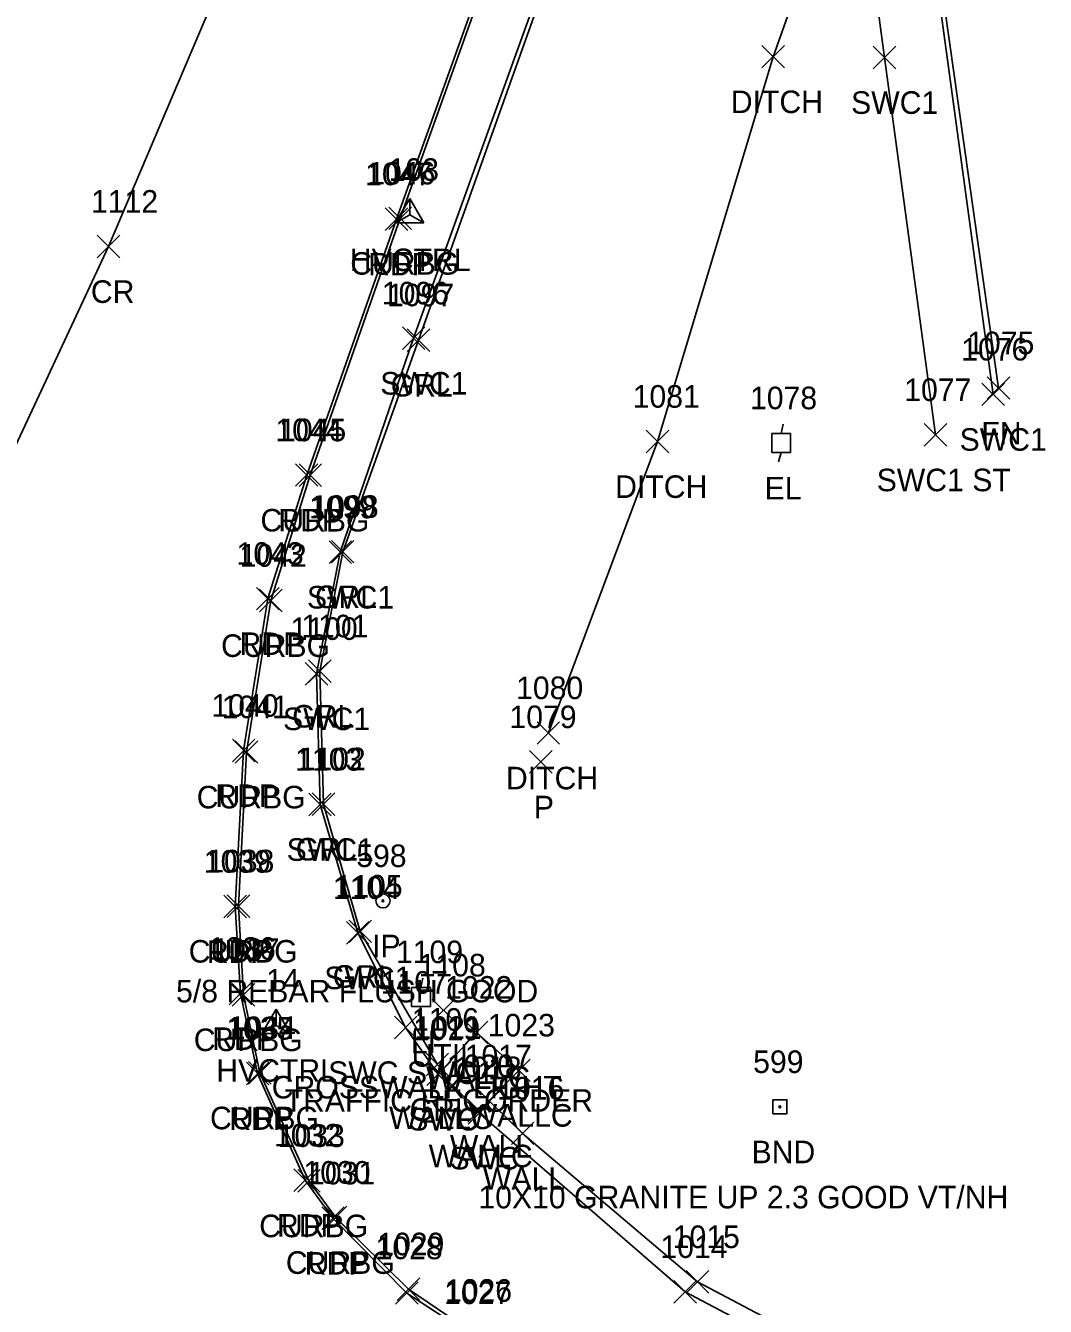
# Model space of a CAD drawing. Extents: x 1690689 to 1696275, y 438760 to 444007.
# Drawn here: x 1693096.4 to 1693186.8, y 438847.7 to 438961.2 of the extents above; entities that cross this region are included whole.
import ezdxf

# ---------------------------------------------------------------- set-up
doc = ezdxf.new("R2010")
doc.units = 0
for name, color, linetype in [('C_A', 7, 'Continuous'), ('C_I', 7, 'Continuous'), ('CPSM', 7, 'Continuous'), ('D_A', 7, 'Continuous'), ('D_I', 7, 'Continuous'), ('D_TIC', 7, 'Continuous'), ('DD', 7, 'Continuous'), ('L_A', 7, 'Continuous'), ('L_I', 7, 'Continuous'), ('L_TIC', 7, 'Continuous'), ('Level 18', 7, 'Continuous'), ('LFNC', 7, 'Continuous'), ('LW', 7, 'Continuous'), ('M_A', 7, 'Continuous'), ('M_C', 7, 'Continuous'), ('M_I', 7, 'Continuous'), ('MPIR', 7, 'Continuous'), ('P_A', 7, 'Continuous'), ('P_I', 7, 'Continuous'), ('P_TIC', 7, 'Continuous'), ('PET', 7, 'Continuous'), ('PRC', 7, 'Continuous'), ('R_A', 7, 'Continuous'), ('R_I', 7, 'Continuous'), ('R_TIC', 7, 'Continuous'), ('RC', 7, 'Continuous'), ('RGR', 7, 'Continuous'), ('RSW', 7, 'Continuous'), ('U_A', 7, 'Continuous'), ('U_C', 7, 'Continuous'), ('U_I', 7, 'Continuous'), ('UDEFAULT', 7, 'Continuous'), ('UEPT', 7, 'Continuous'), ('ULP', 7, 'Continuous')]:
    doc.layers.add(name, color=color, linetype=linetype)

msp = doc.modelspace()

# ---------------------------------------------------------------- linework, layer by layer
at = {"layer": 'CPSM'}
for p, q in [((1693129.22, 438943.73), (1693130.47, 438945.9)), ((1693131.72, 438943.73), (1693130.47, 438945.9)), ((1693130.47, 438944.46), (1693130.47, 438945.9)), ((1693129.22, 438943.73), (1693130.47, 438944.46)), ((1693130.47, 438944.46), (1693130.47, 438944.46)), ((1693130.47, 438944.46), (1693131.72, 438943.73)), ((1693129.22, 438943.73), (1693131.72, 438943.73)), ((1693117.37, 438871.85), (1693118.62, 438874.02)), ((1693119.87, 438871.85), (1693118.62, 438874.02)), ((1693118.62, 438872.58), (1693118.62, 438874.02)), ((1693117.37, 438871.85), (1693118.62, 438872.58)), ((1693118.62, 438872.58), (1693118.62, 438872.58)), ((1693118.62, 438872.58), (1693119.87, 438871.85)), ((1693117.37, 438871.85), (1693119.87, 438871.85))]:
    msp.add_line(p, q, dxfattribs=at)
at = {"layer": 'D_TIC'}
for points in [[(1693161.69, 438957.47), (1693163.69, 438959.47)], [(1693163.69, 438957.47), (1693161.69, 438959.47)], [(1693151.44, 438923.35), (1693153.44, 438925.35)], [(1693153.44, 438923.35), (1693151.44, 438925.35)], [(1693141.76, 438897.51), (1693143.76, 438899.51)], [(1693143.76, 438897.51), (1693141.76, 438899.51)], [(1693141.09, 438894.94), (1693143.09, 438896.94)], [(1693143.09, 438894.94), (1693141.09, 438896.94)]]:
    msp.add_lwpolyline(points, dxfattribs=at)
at = {"layer": 'DD'}
msp.add_lwpolyline([(1693142.76, 438898.51), (1693152.44, 438924.35), (1693162.69, 438958.47), (1693166.84, 438970.21)], dxfattribs=at)
at = {"layer": 'L_TIC'}
for points in [[(1693181.65, 438928.09), (1693183.65, 438930.09)], [(1693183.65, 438928.09), (1693181.65, 438930.09)], [(1693135.38, 438870.95), (1693137.38, 438872.95)], [(1693137.38, 438870.95), (1693135.38, 438872.95)], [(1693132.1, 438867.38), (1693134.1, 438869.38)], [(1693134.1, 438867.38), (1693132.1, 438869.38)], [(1693139.16, 438867.6), (1693141.16, 438869.6)], [(1693141.16, 438867.6), (1693139.16, 438869.6)], [(1693136.55, 438864.86), (1693138.55, 438866.86)], [(1693138.55, 438864.86), (1693136.55, 438866.86)], [(1693135.61, 438864), (1693137.61, 438866)], [(1693137.61, 438864), (1693135.61, 438866)], [(1693139.48, 438862.01), (1693141.48, 438864.01)], [(1693141.48, 438862.01), (1693139.48, 438864.01)], [(1693154.98, 438848.84), (1693156.98, 438850.84)], [(1693156.98, 438848.84), (1693154.98, 438850.84)]]:
    msp.add_lwpolyline(points, dxfattribs=at)
at = {"layer": 'Level 18'}
msp.add_lwpolyline([(1693162.66, 438865.99), (1693163.91, 438865.99), (1693163.91, 438864.74), (1693162.66, 438864.74)], close=True, dxfattribs=at)
msp.add_circle((1693163.28, 438865.36), 0.0833, dxfattribs=at)
at = {"layer": 'LFNC'}
msp.add_lwpolyline([(1693170.07, 439022.53), (1693176.98, 438969.21), (1693182.65, 438929.09)], dxfattribs=at)
at = {"layer": 'LW'}
for points in [[(1693136.61, 438865), (1693133.1, 438868.38), (1693136.38, 438871.95), (1693140.16, 438868.6)], [(1693140.16, 438868.6), (1693136.61, 438865)], [(1693176.44, 438840.23), (1693169.95, 438842.46), (1693155.98, 438849.84), (1693140.48, 438863.01), (1693137.55, 438865.86)]]:
    msp.add_lwpolyline(points, dxfattribs=at)
at = {"layer": 'MPIR'}
for radius in [0.625, 0.0833]:
    msp.add_circle((1693128.1, 438883.62), radius, dxfattribs=at)
at = {"layer": 'P_TIC'}
for points in [[(1693128.29, 438943.07), (1693130.29, 438945.07)], [(1693130.29, 438943.07), (1693128.29, 438945.07)], [(1693102.78, 438940.64), (1693104.78, 438942.64)], [(1693104.78, 438940.64), (1693102.78, 438942.64)], [(1693120.34, 438920.38), (1693122.34, 438922.38)], [(1693122.34, 438920.38), (1693120.34, 438922.38)], [(1693116.89, 438909.42), (1693118.89, 438911.42)], [(1693118.89, 438909.42), (1693116.89, 438911.42)], [(1693114.75, 438895.95), (1693116.75, 438897.95)], [(1693116.75, 438895.95), (1693114.75, 438897.95)], [(1693114, 438882.12), (1693116, 438884.12)], [(1693116, 438882.12), (1693114, 438884.12)], [(1693114.47, 438874.4), (1693116.47, 438876.4)], [(1693116.47, 438874.4), (1693114.47, 438876.4)], [(1693115.99, 438867.32), (1693117.99, 438869.32)], [(1693117.99, 438867.32), (1693115.99, 438869.32)], [(1693120.21, 438857.85), (1693122.21, 438859.85)], [(1693122.21, 438857.85), (1693120.21, 438859.85)], [(1693122.67, 438854.48), (1693124.67, 438856.48)], [(1693124.67, 438854.48), (1693122.67, 438856.48)], [(1693129.21, 438847.85), (1693131.21, 438849.85)], [(1693131.21, 438847.85), (1693129.21, 438849.85)]]:
    msp.add_lwpolyline(points, dxfattribs=at)
at = {"layer": 'PET'}
msp.add_lwpolyline([(1693178, 438831.35), (1693167.86, 438834.18), (1693150.55, 438839.03), (1693143.37, 438841.6), (1693136.29, 438844.87), (1693130.21, 438848.85), (1693123.67, 438855.48), (1693121.21, 438858.85), (1693116.99, 438868.32), (1693115.47, 438875.4), (1693115, 438883.12), (1693115.75, 438896.95), (1693117.89, 438910.42), (1693121.34, 438921.38), (1693129.29, 438944.07), (1693138.23, 438969.02), (1693143.65, 438986.67), (1693149.76, 439012.35), (1693154.07, 439032.19), (1693155.34, 439035.22), (1693157.21, 439037.36), (1693158.65, 439037.84), (1693160.14, 439048.77), (1693162.88, 439071.43)], dxfattribs=at)
at = {"layer": 'PRC'}
msp.add_lwpolyline([(1693075.4, 438881.17), (1693089.6, 438911.3), (1693103.78, 438941.64), (1693117.42, 438973.77), (1693128.92, 439005.9), (1693137.63, 439039.04), (1693143.37, 439073.85)], dxfattribs=at)
at = {"layer": 'R_TIC'}
for points in [[(1693171.55, 438957.4), (1693173.55, 438959.4)], [(1693173.55, 438957.4), (1693171.55, 438959.4)], [(1693128.62, 438943.14), (1693130.62, 438945.14)], [(1693130.62, 438943.14), (1693128.62, 438945.14)], [(1693129.82, 438932.51), (1693131.82, 438934.51)], [(1693131.82, 438932.51), (1693129.82, 438934.51)], [(1693130.24, 438932.34), (1693132.24, 438934.34)], [(1693132.24, 438932.34), (1693130.24, 438934.34)], [(1693181.18, 438927.53), (1693183.18, 438929.53)], [(1693183.18, 438927.53), (1693181.18, 438929.53)], [(1693176.08, 438923.94), (1693178.08, 438925.94)], [(1693178.08, 438923.94), (1693176.08, 438925.94)], [(1693120.66, 438920.37), (1693122.66, 438922.37)], [(1693122.66, 438920.37), (1693120.66, 438922.37)], [(1693123.32, 438913.54), (1693125.32, 438915.54)], [(1693125.32, 438913.54), (1693123.32, 438915.54)], [(1693123.53, 438913.58), (1693125.53, 438915.58)], [(1693125.53, 438913.58), (1693123.53, 438915.58)], [(1693117.16, 438909.25), (1693119.16, 438911.25)], [(1693119.16, 438909.25), (1693117.16, 438911.25)], [(1693121.2, 438902.76), (1693123.2, 438904.76)], [(1693123.2, 438902.76), (1693121.2, 438904.76)], [(1693121.5, 438902.99), (1693123.5, 438904.99)], [(1693123.5, 438902.99), (1693121.5, 438904.99)], [(1693115, 438895.82), (1693117, 438897.82)], [(1693117, 438895.82), (1693115, 438897.82)], [(1693121.52, 438891.17), (1693123.52, 438893.17)], [(1693123.52, 438891.17), (1693121.52, 438893.17)], [(1693121.82, 438891.2), (1693123.82, 438893.2)], [(1693123.82, 438891.2), (1693121.82, 438893.2)], [(1693114.29, 438882.15), (1693116.29, 438884.15)], [(1693116.29, 438882.15), (1693114.29, 438884.15)], [(1693124.86, 438879.79), (1693126.86, 438881.79)], [(1693126.86, 438879.79), (1693124.86, 438881.79)], [(1693125.09, 438879.92), (1693127.09, 438881.92)], [(1693127.09, 438879.92), (1693125.09, 438881.92)], [(1693114.74, 438874.3), (1693116.74, 438876.3)], [(1693116.74, 438874.3), (1693114.74, 438876.3)], [(1693129.11, 438871.39), (1693131.11, 438873.39)], [(1693131.11, 438871.39), (1693129.11, 438873.39)], [(1693129.11, 438871.39), (1693131.11, 438873.39)], [(1693131.11, 438871.39), (1693129.11, 438873.39)], [(1693131.92, 438868.11), (1693133.92, 438870.11)], [(1693133.92, 438868.11), (1693131.92, 438870.11)], [(1693116.19, 438867.37), (1693118.19, 438869.37)], [(1693118.19, 438867.37), (1693116.19, 438869.37)], [(1693131.98, 438867.26), (1693133.98, 438869.26)], [(1693133.98, 438867.26), (1693131.98, 438869.26)], [(1693135.64, 438863.81), (1693137.64, 438865.81)], [(1693137.64, 438863.81), (1693135.64, 438865.81)], [(1693120.54, 438857.8), (1693122.54, 438859.8)], [(1693122.54, 438857.8), (1693120.54, 438859.8)], [(1693122.91, 438854.55), (1693124.91, 438856.55)], [(1693124.91, 438854.55), (1693122.91, 438856.55)], [(1693129.37, 438848.2), (1693131.37, 438850.2)], [(1693131.37, 438848.2), (1693129.37, 438850.2)], [(1693153.89, 438847.96), (1693155.89, 438849.96)], [(1693155.89, 438847.96), (1693153.89, 438849.96)]]:
    msp.add_lwpolyline(points, dxfattribs=at)
at = {"layer": 'RC'}
msp.add_lwpolyline([(1693178.03, 438831.53), (1693167.9, 438834.34), (1693150.57, 438839.37), (1693143.21, 438842), (1693136.42, 438845.08), (1693130.37, 438849.2), (1693123.91, 438855.55), (1693121.54, 438858.8), (1693117.19, 438868.37), (1693115.74, 438875.3), (1693115.29, 438883.15), (1693116, 438896.82), (1693118.16, 438910.25), (1693121.66, 438921.37), (1693129.62, 438944.14), (1693138.48, 438968.95), (1693143.79, 438986.67), (1693150.08, 439012.32), (1693154.23, 439032.31)], dxfattribs=at)
at = {"layer": 'RGR'}
msp.add_lwpolyline([(1693159.79, 438999.34), (1693153.67, 438991.77), (1693151.07, 438986.95), (1693144.82, 438971.39), (1693131.24, 438933.34), (1693124.53, 438914.58), (1693122.5, 438903.99), (1693122.82, 438892.2), (1693126.09, 438880.92), (1693132.92, 438869.11)], dxfattribs=at)
at = {"layer": 'RSW'}
for points in [[(1693154.23, 439032.31), (1693155.6, 439035.22), (1693157.23, 439037.18), (1693159.3, 439037.74), (1693163.18, 439035.96), (1693167.65, 439031.6), (1693169.75, 439022.56), (1693176.65, 438969.04), (1693182.18, 438928.53)], [(1693177.08, 438924.94), (1693172.55, 438958.4), (1693164.75, 439016.33), (1693163.48, 439025.83), (1693161.01, 439030.23), (1693158.92, 439031.14), (1693149.55, 438988.8), (1693144.42, 438971.31), (1693130.82, 438933.51), (1693124.32, 438914.54), (1693122.2, 438903.76), (1693122.52, 438892.17), (1693125.86, 438880.79), (1693130.11, 438872.39)], [(1693179.46, 438837.75), (1693169.64, 438841.15), (1693154.89, 438848.96), (1693136.64, 438864.81), (1693132.98, 438868.26), (1693130.11, 438872.39)]]:
    msp.add_lwpolyline(points, dxfattribs=at)
at = {"layer": 'UDEFAULT'}
for points in [[(1693132.47, 438872.92), (1693134.47, 438874.92)], [(1693134.47, 438872.92), (1693132.47, 438874.92)]]:
    msp.add_lwpolyline(points, dxfattribs=at)
at = {"layer": 'UEPT'}
for p, q in [((1693163.56, 438925.88), (1693163.4, 438925.05)), ((1693162.56, 438923.38), (1693162.56, 438925.05)), ((1693162.56, 438925.05), (1693164.23, 438925.05)), ((1693164.23, 438925.05), (1693164.23, 438923.38)), ((1693163.4, 438924.21), (1693163.4, 438924.21)), ((1693164.23, 438923.38), (1693162.56, 438923.38)), ((1693163.15, 438922.55), (1693163.4, 438923.38))]:
    msp.add_line(p, q, dxfattribs=at)
at = {"layer": 'ULP'}
for p, q in [((1693130.63, 438874.27), (1693130.63, 438875.94)), ((1693130.63, 438875.94), (1693132.3, 438875.94)), ((1693131.63, 438876.77), (1693131.46, 438875.94)), ((1693132.3, 438875.94), (1693132.3, 438874.27)), ((1693131.46, 438875.1), (1693131.46, 438875.1)), ((1693132.3, 438874.27), (1693130.63, 438874.27)), ((1693131.21, 438873.44), (1693131.46, 438874.27))]:
    msp.add_line(p, q, dxfattribs=at)

# ---------------------------------------------------------------- texts
at = {"layer": 'C_A'}
for p in [(1693125.16, 438939.46), (1693113.32, 438867.58)]:
    msp.add_text('HVCTRL', height=2, dxfattribs=at).set_placement(p)
at = {"layer": 'C_I'}
for s, p in [('103', (1693128.6, 438947.46)), ('14', (1693117.73, 438875.57))]:
    msp.add_text(s, height=2, dxfattribs=at).set_placement(p)
at = {"layer": 'D_A'}
for s, p in [('DITCH', (1693158.93, 438953.47)), ('DITCH', (1693148.68, 438919.35)), ('DITCH', (1693139, 438893.51)), ('P', (1693141.47, 438890.94))]:
    msp.add_text(s, height=2, dxfattribs=at).set_placement(p)
at = {"layer": 'D_I'}
for s, p in [('1081', (1693150.23, 438927.35)), ('1080', (1693139.9, 438901.51)), ('1079', (1693139.31, 438898.94))]:
    msp.add_text(s, height=2, dxfattribs=at).set_placement(p)
at = {"layer": 'L_A'}
for s, p in [('FN', (1693181.13, 438924.09)), ('WALLC', (1693131.92, 438866.95)), ('WALLC', (1693135.7, 438863.6)), ('WALLC', (1693128.63, 438863.38)), ('WALL', (1693134.03, 438860.86)), ('WALLC', (1693132.15, 438860)), ('WALL', (1693136.96, 438858.01))]:
    msp.add_text(s, height=2, dxfattribs=at).set_placement(p)
at = {"layer": 'L_I'}
for s, p in [('1075', (1693179.88, 438932.09)), ('1022', (1693133.61, 438874.95)), ('1023', (1693137.39, 438871.6)), ('1021', (1693130.89, 438871.38)), ('1017', (1693135.34, 438868.86)), ('1020', (1693133.75, 438868)), ('1016', (1693138.22, 438866.01)), ('1015', (1693153.78, 438852.84))]:
    msp.add_text(s, height=2, dxfattribs=at).set_placement(p)
at = {"layer": 'M_A'}
for s, p in [('IP', (1693127.14, 438878.62)), ('BND', (1693160.77, 438860.36))]:
    msp.add_text(s, height=2, dxfattribs=at).set_placement(p)
at = {"layer": 'M_C'}
for s, p in [('5/8 REBAR FLUSH GOOD', (1693109.76, 438874.62)), ('10X10 GRANITE UP 2.3 GOOD VT/NH', (1693136.56, 438856.36))]:
    msp.add_text(s, height=2, dxfattribs=at).set_placement(p)
at = {"layer": 'M_I'}
for s, p in [('598', (1693125.73, 438886.62)), ('599', (1693160.91, 438868.36))]:
    msp.add_text(s, height=2, dxfattribs=at).set_placement(p)
at = {"layer": 'P_A'}
for s, p in [('RDP', (1693126.78, 438939.07)), ('CR', (1693102.21, 438936.64)), ('RDP', (1693118.82, 438916.38)), ('RDP', (1693115.38, 438905.42)), ('RDP', (1693113.24, 438891.95)), ('RDP', (1693112.48, 438878.12)), ('RDP', (1693112.96, 438870.4)), ('RDP', (1693114.47, 438863.32)), ('RDP', (1693118.7, 438853.85)), ('RDP', (1693121.16, 438850.48))]:
    msp.add_text(s, height=2, dxfattribs=at).set_placement(p)
at = {"layer": 'P_I'}
for s, p in [('1047', (1693126.52, 438947.07)), ('1112', (1693102.22, 438944.64)), ('1044', (1693118.56, 438924.38)), ('1043', (1693115.12, 438913.42)), ('1040', (1693112.89, 438899.95)), ('1039', (1693112.22, 438886.12)), ('1036', (1693112.65, 438878.4)), ('1035', (1693114.21, 438871.32)), ('1032', (1693118.44, 438861.85)), ('1031', (1693121.46, 438858.48)), ('1028', (1693127.44, 438851.85)), ('1027', (1693133.52, 438847.87))]:
    msp.add_text(s, height=2, dxfattribs=at).set_placement(p)
at = {"layer": 'R_A'}
for s, p in [('SWC1', (1693169.59, 438953.4)), ('CURBG', (1693125.2, 438939.14)), ('SWC1', (1693127.86, 438928.51)), ('GRL', (1693128.78, 438928.34)), ('SWC1', (1693179.21, 438923.53)), ('SWC1 ST', (1693171.86, 438919.94)), ('CURBG', (1693117.24, 438916.37)), ('SWC1', (1693121.36, 438909.54)), ('GRL', (1693122.07, 438909.58)), ('CURBG', (1693113.75, 438905.25)), ('SWC1', (1693119.24, 438898.76)), ('GRL', (1693120.05, 438898.99)), ('CURBG', (1693111.59, 438891.82)), ('SWC1', (1693119.56, 438887.17)), ('GRL', (1693120.37, 438887.2)), ('CURBG', (1693110.88, 438878.15)), ('SWC1', (1693122.9, 438875.79)), ('GRL', (1693123.64, 438875.92)), ('CURBG', (1693111.33, 438870.3)), ('SWC SWC1', (1693123.24, 438867.39)), ('SWC SWC1', (1693123.24, 438867.39)), ('GRL', (1693130.46, 438864.11)), ('CURBG', (1693112.77, 438863.37)), ('SWC', (1693130.34, 438863.26)), ('SWC', (1693134, 438859.81)), ('CURBG', (1693117.13, 438853.8)), ('CURBG', (1693119.49, 438850.55))]:
    msp.add_text(s, height=2, dxfattribs=at).set_placement(p)
at = {"layer": 'R_I'}
for s, p in [('1046', (1693126.79, 438947.14)), ('1096', (1693128, 438936.51)), ('1097', (1693128.46, 438936.34)), ('1076', (1693179.35, 438931.53)), ('1077', (1693174.3, 438927.94)), ('1045', (1693118.89, 438924.37)), ('1099', (1693121.54, 438917.54)), ('1098', (1693121.76, 438917.58)), ('1042', (1693115.39, 438913.25)), ('1100', (1693119.91, 438906.76)), ('1101', (1693120.86, 438906.99)), ('1041', (1693113.8, 438899.82)), ('1103', (1693120.31, 438895.17)), ('1102', (1693120.62, 438895.2)), ('1038', (1693112.52, 438886.15)), ('1104', (1693123.66, 438883.79)), ('1105', (1693123.89, 438883.92)), ('1037', (1693112.97, 438878.3)), ('1107', (1693127.9, 438875.39)), ('1107', (1693127.9, 438875.39)), ('1106', (1693130.66, 438872.11)), ('1034', (1693114.42, 438871.37)), ('1019', (1693130.77, 438871.26)), ('1018', (1693134.44, 438867.81)), ('1033', (1693118.77, 438861.8)), ('1030', (1693121.05, 438858.55)), ('1029', (1693127.59, 438852.2)), ('1014', (1693152.69, 438851.96)), ('1026', (1693133.59, 438848.08))]:
    msp.add_text(s, height=2, dxfattribs=at).set_placement(p)
at = {"layer": 'U_A'}
for s, p in [('EL', (1693161.93, 438919.21)), ('LI', (1693130.57, 438870.1)), ('UTIL', (1693130.63, 438868.92))]:
    msp.add_text(s, height=2, dxfattribs=at).set_placement(p)
at = {"layer": 'U_C'}
for s, p in [('CROSSWALK LIGHT', (1693118.24, 438866.1)), ('TRAFFIC RECORDER', (1693119.38, 438864.92))]:
    msp.add_text(s, height=2, dxfattribs=at).set_placement(p)
at = {"layer": 'U_I'}
for s, p in [('1078', (1693160.63, 438927.21)), ('1109', (1693129.25, 438878.1)), ('1108', (1693131.26, 438876.92))]:
    msp.add_text(s, height=2, dxfattribs=at).set_placement(p)

doc.saveas('drawing.dxf')
